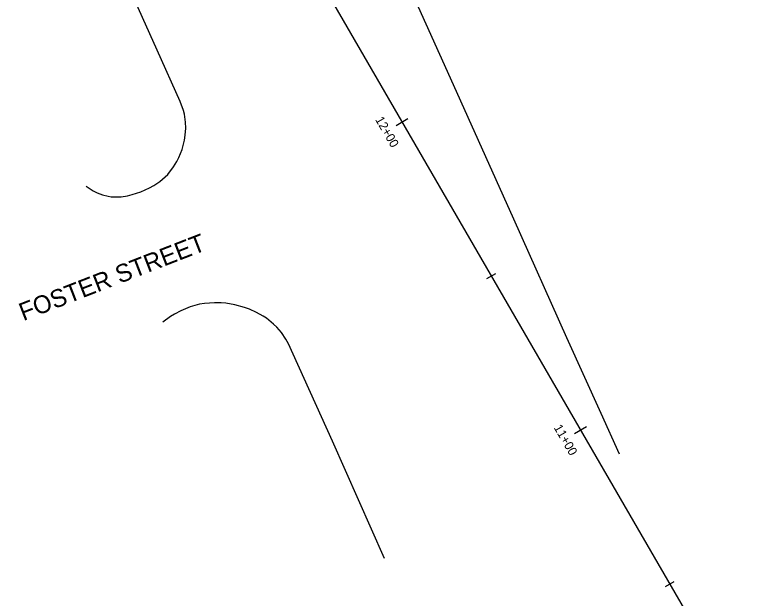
# Model space of a CAD drawing. Extents: x 359002 to 1164845, y 1141798 to 1525369.
# Drawn here: x 1164488.9 to 1164697.9, y 1141958.5 to 1142122.3 of the extents above; entities that cross this region are included whole.
import ezdxf

# ---------------------------------------------------------------- set-up
doc = ezdxf.new("R2010")
doc.units = 0
for name, color, linetype in [('ACSR_P_T', 7, 'Continuous'), ('CB', 7, 'Continuous'), ('PE', 7, 'Continuous'), ('PRC_C', 7, 'Continuous')]:
    doc.layers.add(name, color=color, linetype=linetype)

msp = doc.modelspace()

# ---------------------------------------------------------------- linework, layer by layer
at = {"layer": 'ACSR_P_T'}
for points in [[(1164595.97, 1142091.29), (1164599.29, 1142093.21)], [(1164621.46, 1142048.27), (1164623.95, 1142049.72)], [(1164646.12, 1142004.77), (1164649.45, 1142006.7)], [(1164671.61, 1141961.76), (1164674.11, 1141963.2)]]:
    msp.add_lwpolyline(points, dxfattribs=at)
at = {"layer": 'CB'}
msp.add_line((1164291, 1142621.19), (1164697.94, 1141919.22), dxfattribs=at)
at = {"layer": 'PE'}
for points in [[(1164591.52, 1142148.41), (1164611.14, 1142104.63), (1164628.94, 1142065.06), (1164643.87, 1142031.72), (1164653.47, 1142010.42), (1164658.62, 1141999.01)], [(1164508.89, 1142074.17), (1164510.93, 1142072.89), (1164511.97, 1142072.37), (1164513.54, 1142071.77), (1164515.14, 1142071.37), (1164515.96, 1142071.26), (1164516.87, 1142071.19), (1164518.71, 1142071.26), (1164520.57, 1142071.54), (1164521.81, 1142071.83), (1164524.23, 1142072.63), (1164526.73, 1142073.74), (1164527.91, 1142074.4), (1164529.59, 1142075.51), (1164531.12, 1142076.8), (1164531.82, 1142077.5), (1164533.48, 1142079.6), (1164534.41, 1142081.15), (1164534.95, 1142082.22), (1164535.85, 1142084.47), (1164536.56, 1142087.15), (1164536.77, 1142088.51), (1164536.91, 1142090.55), (1164536.85, 1142092.21), (1164536.5, 1142094.42), (1164536.22, 1142095.51), (1164535.31, 1142097.97), (1164528.82, 1142112.4), (1164522.66, 1142126.22)], [(1164592.72, 1141969.63), (1164578.1, 1142002.57), (1164567.08, 1142027.03), (1164565.74, 1142029.89), (1164565.01, 1142031.25), (1164563.75, 1142033.16), (1164562.5, 1142034.61), (1164561.58, 1142035.5), (1164559.55, 1142037.1), (1164558.65, 1142037.7), (1164556.76, 1142038.77), (1164554.8, 1142039.66), (1164553.44, 1142040.16), (1164550.65, 1142040.91), (1164548.14, 1142041.32), (1164546.88, 1142041.43), (1164544.99, 1142041.48), (1164542.18, 1142041.27), (1164540.8, 1142041.03), (1164538.09, 1142040.3), (1164535.48, 1142039.21), (1164533.77, 1142038.3), (1164532.65, 1142037.6), (1164530.45, 1142036.01)]]:
    msp.add_lwpolyline(points, dxfattribs=at)

# ---------------------------------------------------------------- texts
at = {"layer": 'ACSR_P_T'}
for s, p in [('12+00', (1164590.02, 1142092.93)), ('11+00', (1164640.17, 1142006.42))]:
    msp.add_text(s, height=2.501, rotation=300.1015, dxfattribs=at).set_placement(p)
at = {"layer": 'PRC_C'}
msp.add_text('FOSTER STREET', height=5.0016, rotation=21.2078, dxfattribs=at).set_placement((1164491.27, 1142036.3))

doc.saveas('drawing.dxf')
